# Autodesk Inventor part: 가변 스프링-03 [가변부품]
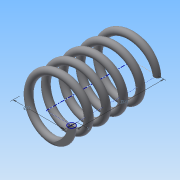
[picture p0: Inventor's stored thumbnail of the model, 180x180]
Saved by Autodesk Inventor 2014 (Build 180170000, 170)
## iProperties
Created: 2015-09
Part Number: 가변 스프링-03 [가변부품]
Material: 강철, 탄소
Document SubType Name: Modeling
Designer: study
Density: 1 g/cm^3
Appearance: 반연마
Author: study
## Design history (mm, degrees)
sketch "스케치1"
  geometry: L1 (0, 0)-(11, 0); L2 (11, 0)-(11, 36.411); L3 (11, 36.411)-(0, 36.411); L4 (0, 36.411)-(0, 0); C1 r 1.5 at (11, 0)
  constraints: 8 end point, 2 parallel, 1 centre point, 1 coincident, 1 horizontal, 1 perpendicular
  dimensions: "d0" = 3 diameter of C1; "d1" = 22 diameter of L2 L4; "d2" = 36.4112 distance of L1.end L2.end (derived)
feature "코일1" sketch "스케치1" pitch "d3" = 10; turns "d5" = 5; dims "d4" = 36.4112 (= d2), "d6" = 0, angle "d7" = 90 deg, angle "d8" = 90 deg, "d9" = 0, "d10" = 0
node "작업 평면1"
sketch "스케치2"
  geometry: L1 (-12.5, 0)-(-9.5, 0) reference; 1 further point
  constraints: 1 horizontal alignment
extrude "돌출1" cut sketch "스케치2" distance "d12" = 10; taper "d13" = 0 deg
node "작업 평면2"
sketch "스케치3"
  geometry: L1 (-9.5, 0)-(-12.5, 0) reference; L2 (-9.5, 0)-(-12.5, 0) reference; 1 further point
  constraints: 2 horizontal alignment
extrude "돌출2" cut sketch "스케치3" distance "d15" = 10; taper "d16" = 0 deg
node "솔리드1"
node "절단 모서리 투영1"
node "절단 모서리 투영2"
node "절단 모서리 투영3"
other parameters: "d11" = 0, "d14" = 36.4112 (= d2)
